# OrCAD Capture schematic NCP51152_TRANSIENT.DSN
size B; title: NCP51152xA & NCP51152xB; rev: 0
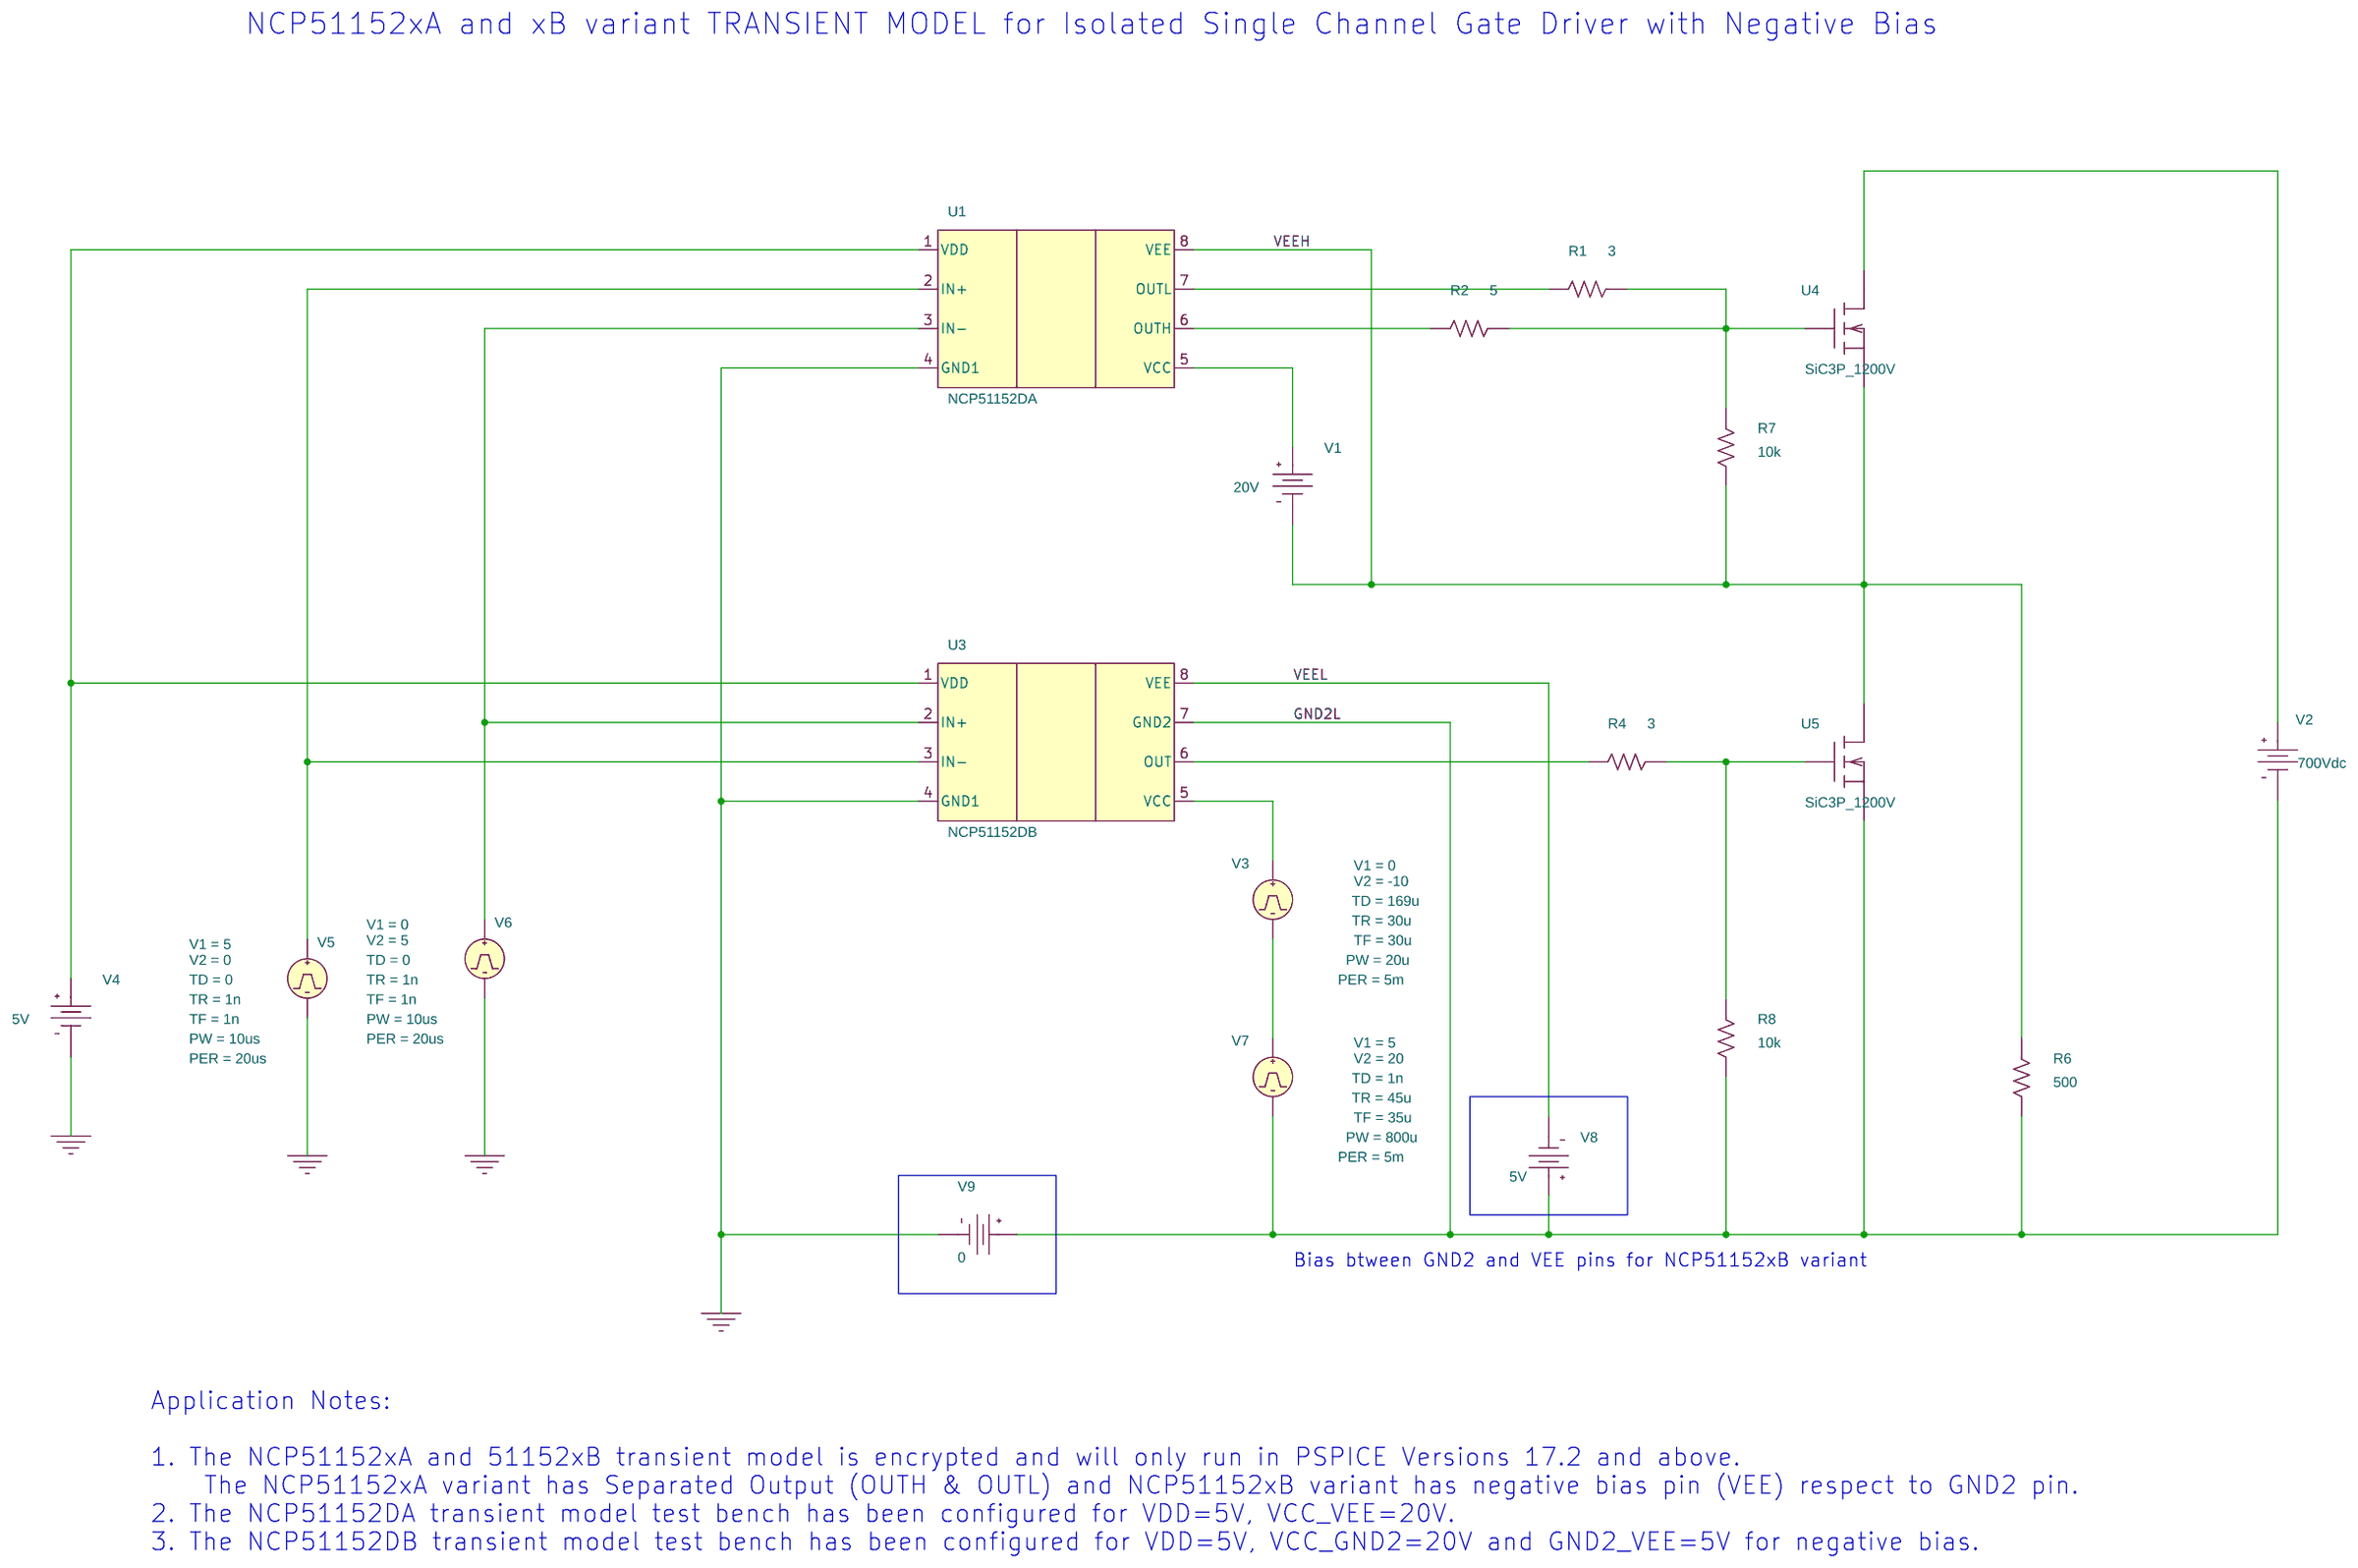
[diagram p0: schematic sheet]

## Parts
R1  3  [AX/RC05]
R2  5  [AX/RC05]
R4  3  [AX/RC05]
R6  500  [AX/RC05]
R7  10k  [AX/RC05]
R8  10k  [AX/RC05]
U1  NCP51152DA
U3  NCP51152DB
U4  SiC3P_1200V
U5  SiC3P_1200V
V1  VDC
V2  VDC
V3  VPULSE
V4  VDC
V5  VPULSE
V6  VPULSE
V7  VPULSE
V8  VDC
V9  VDC

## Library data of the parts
R1 R2 R4 R6-R8 = R
U1 = NCP51152DA
U3 = NCP51152DB
U4 U5 = SICMOSFET_3P
V1 = VDC: DC: 20V
V2 = VDC: DC: 700Vdc
V3 = VPULSE: PER: 5m; PW: 20u; TD: 169u; TF: 30u; TR: 30u; V1: 0; V2: -10
V4 V8 = VDC: DC: 5V
V5 = VPULSE: PER: 20us; PW: 10us; TD: 0; TF: 1n; TR: 1n; V1: 5; V2: 0
V6 = VPULSE: PER: 20us; PW: 10us; TD: 0; TF: 1n; TR: 1n; V1: 0; V2: 5
V7 = VPULSE: PER: 5m; PW: 800u; TD: 1n; TF: 35u; TR: 45u; V1: 5; V2: 20
V9 = VDC: DC: 0

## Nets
GND2L: R6.2 R8.2 U3.7(GND2) U5.3(S) V2.1(-) V7.2(-) V8.0(+) V9.0(+)
VEEH: R6.1 R7.2 U1.8(VEE) U4.3(S) U5.1(D) V1.1(-)
VEEL: U3.8(VEE) V8.1(-)
0: U1.4(GND1) U3.4(GND1) V4.1(-) V5.2(-) V6.2(-) V9.1(-)
N16958254: R4.1 R8.1 U5.2(G)
N17012757: U3.5(VCC) V3.1(+)
N17012769: R4.2 U3.6(OUT)
N17012960: U1.1(VDD) U3.1(VDD) V4.0(+)
N17012965: U1.2(IN+) U3.3(IN-) V5.1(+)
N17013085: R1.1 R2.1 R7.1 U4.2(G)
N17013146: R1.2 U1.7(OUTL)
N17013202: U4.1(D) V2.0(+)
N17013284: U1.5(VCC) V1.0(+)
N17013372: U1.3(IN-) U3.2(IN+) V6.1(+)
N17013893: V3.2(-) V7.1(+)
N17014578: R2.2 U1.6(OUTH)

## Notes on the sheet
- NCP51152xA and xB variant TRANSIENT MODEL for Isolated Single Channel Gate Driver with Negative Bias
- Bias btween GND2 and VEE pins for NCP51152xB variant
- Application Notes:
  1. The NCP51152xA and 51152xB transient model is encrypted and will only run in PSPICE Versions 17.2 and above.
      The NCP51152xA variant has Separated Output (OUTH & OUTL) and NCP51152xB variant has negative bias pin (VEE) respect to GND2 pin.
  2. The NCP51152DA transient model test bench has been configured for VDD=5V, VCC_VEE=20V.
  3. The NCP51152DB transient model test bench has been configured for VDD=5V, VCC_GND2=20V and GND2_VEE=5V for negative bias.
